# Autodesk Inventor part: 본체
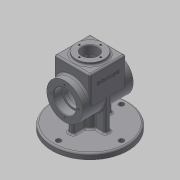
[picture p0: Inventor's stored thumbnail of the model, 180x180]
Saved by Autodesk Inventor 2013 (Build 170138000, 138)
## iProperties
Created: 2020-07
Part Number: 본체
Material: 일반
Document SubType Name: Modeling
Designer: mduedu
Density: 1 g/cm^3
Author: mduedu
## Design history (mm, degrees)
sketch "스케치1"
  geometry: C1 r 32 at (0, 0); 1 further point
  constraints: 1 centre point, 1 coincident
  dimensions: "d0" = 64 diameter of C1
extrude "돌출1" new body sketch "스케치1" stored distance "d1" = 90; taper "d2" = 0 deg
sketch "스케치3"
  geometry: L1 (0, -32)-(50, -32); L2 (50, -32)-(50, 32); L3 (50, 32)-(0, 32); L4 (0, 32)-(0, -32); C1 r 32 at (0, 0) reference; 2 further points
  constraints: 8 end point, 2 parallel, 1 coincident, 1 horizontal, 1 midpoint, 1 perpendicular, 1 tangent
  dimensions: "d5" = 50 distance of L2.end L3.end
extrude "돌출2" join sketch "스케치3" stored distance "d7" = 64; taper "d8" = 0 deg
sketch "스케치4"
  geometry: C1 r 25 at (32, 32); 1 further point
  constraints: 1 centre point, 1 coincident
  dimensions: "d9" = 50 diameter of C1
extrude "돌출3" join sketch "스케치4" distance "d10" = 5; taper "d11" = 0 deg
sketch "스케치5"
  geometry: L1 (0, -25)-(40, -25); L2 (40, -25)-(40, 25); L3 (40, 25)-(0, 25); L4 (0, 25)-(0, -25); L5 (55, -25)-(55, 25) reference; A1 r 25 centre (0, 0) between (0, 25) and (0, -25); A2 r 25 centre (0, 0) between (0, -25) and (0, 25); 2 further points
  constraints: 8 end point, 4 point on circle, 2 centre point, 2 coincident, 2 parallel, 1 horizontal, 1 midpoint, 1 perpendicular, 1 tangent
  dimensions: "d12" = 50 diameter of A1; "d13" = 15 distance between parallel lines of L2 L5
extrude "돌출4" cut sketch "스케치5" stored distance "d14" = 48; taper "d15" = 0 deg
sketch "스케치6"
  geometry: C1 r 20 at (0, 0); 1 further point
  constraints: 1 centre point, 1 coincident
  dimensions: "d16" = 40 diameter of C1
extrude "돌출5" cut sketch "스케치6" distance "d17" = 15; taper "d18" = 0 deg
sketch "스케치7"
  geometry: C1 r 17 at (0, 0); 1 further point
  constraints: 1 centre point, 1 coincident
  dimensions: "d19" = 34 diameter of C1
extrude "돌출6" cut sketch "스케치7" stored distance "d20" = 15; taper "d21" = 0 deg
fillet "모깎기1" dims "d22" = 3
fillet "모깎기2" dims "d23" = 3
fillet "모깎기3" dims "d24" = 3
fillet "모깎기4" dims "d25" = 3
fillet "모깎기5" dims "d26" = 3
sketch "스케치8"
  geometry: C1 r 14 at (0, 0); 1 further point
  constraints: 1 centre point, 1 coincident
  dimensions: "d27" = 28 diameter of C1
extrude "돌출7" cut sketch "스케치8" stored distance "d28" = 15; taper "d29" = 0 deg
node "작업 평면1"
sketch "스케치9"
  geometry: C1 r 67.5 at (0, 0); 1 further point
  constraints: 1 centre point, 1 coincident
  dimensions: "d31" = 135 diameter of C1
extrude "돌출8" join sketch "스케치9" distance "d33" = 10; taper "d34" = 0 deg
sketch "스케치10"
  geometry: C1 r 15 at (0, 0); 1 further point
  constraints: 1 centre point, 1 coincident
  dimensions: "d35" = 30 diameter of C1
extrude "돌출9" join sketch "스케치10" stored distance "d39" = 10; taper "d40" = 0 deg
sketch "스케치11"
  geometry: L1 (-35, -5)-(35, -5); L2 (35, -5)-(35, 5); L3 (35, 5)-(-35, 5); L4 (-35, 5)-(-35, -5); L5 (-35, -5)-(35, 5); L6 (35, -5)-(-35, 5); 1 further point
  constraints: 12 end point, 2 midpoint, 2 parallel, 1 horizontal, 1 perpendicular
  dimensions: "d41" = 70 distance of L3.end L2.end; "d42" = 10 distance of L2.end L1.end
extrude "돌출10" join sketch "스케치11" stored distance "d43" = 10; taper "d44" = 0 deg
sketch "스케치12"
  geometry: L1 (-5, -32)-(5, -32); L2 (5, -32)-(5, 32); L3 (5, 32)-(-5, 32); L4 (-5, 32)-(-5, -32); L5 (-5, -32)-(5, 32); L6 (5, -32)-(-5, 32); 1 further point
  constraints: 12 end point, 2 midpoint, 2 parallel, 1 horizontal, 1 perpendicular
  dimensions: "d45" = 10 distance of L3.end L2.end; "d46" = 64 distance of L2.end L1.end
extrude "돌출11" join sketch "스케치12" stored distance "d47" = 10; taper "d48" = 0 deg
fillet "모깎기6" dims "d50" = 3
fillet "모깎기7" dims "d51" = 3
sketch "스케치13" dims "d52" = 112
  geometry: 3 further points
  constraints: 2 horizontal alignment, 1 coincident, 2 other
hole "구멍1" sketch "스케치13" at (-56, 0) diameter "d54" = 9; stored, may be unused: countersink angle "d58" = 90 deg, drill point angle "d60" = 118 deg; dims "d55" = 6, "d56" = 4, "d57" = 2, "d59" = 8
fillet "모깎기8" dims "d64" = 3
sketch "스케치14" dims "d67" = 50
  geometry: 3 further points
  constraints: 2 vertical alignment, 1 coincident, 2 other
hole "구멍2" sketch "스케치14" at (0, 25) diameter "d68" = 3.242; stored, may be unused: countersink angle "d72" = 90 deg, drill point angle "d74" = 118 deg; dims "d69" = 7, "d70" = 4, "d71" = 2, "d73" = 9
sketch "스케치15" dims "d78" = 38
  geometry: 3 further points
  constraints: 2 vertical alignment, 1 coincident, 2 other
hole "구멍3" sketch "스케치15" at (0, 19) diameter "d79" = 3.242; stored, may be unused: countersink angle "d83" = 90 deg, drill point angle "d85" = 118 deg; dims "d80" = 8, "d81" = 4, "d82" = 2, "d84" = 10
fillet "모깎기9" dims "d89" = 0.3
chamfer "모따기1" distance "d90" = 1; stored, may be unused: second distance "d91" = 2, angle "d92" = 45 deg
chamfer "모따기2" distance "d93" = 1; stored, may be unused: second distance "d94" = 2, angle "d95" = 45 deg
sketch "스케치16"
  geometry: L1 (-3, 0)-(-3, -27.404) reference; L2 (54, 8)-(4, 8) reference; 2 further points
  constraints: 1 other
  dimensions: "d96" = 32 distance from line of point (29, -17) L1; "d97" = 25 distance from line of point (29, -17) L2
feature "엠보싱1" sketch "스케치16" dims "d0" = 64, "d98" = 0.5, "d99" = 0
node "솔리드1"
mirror "대칭1"
pattern_circular "원형 패턴1" dims angle "d62" = 360 deg
pattern_circular "원형 패턴2" dims angle "d76" = 360 deg
mirror "대칭2"
pattern_circular "원형 패턴3" dims angle "d87" = 360 deg
other parameters: "d30" = -65
